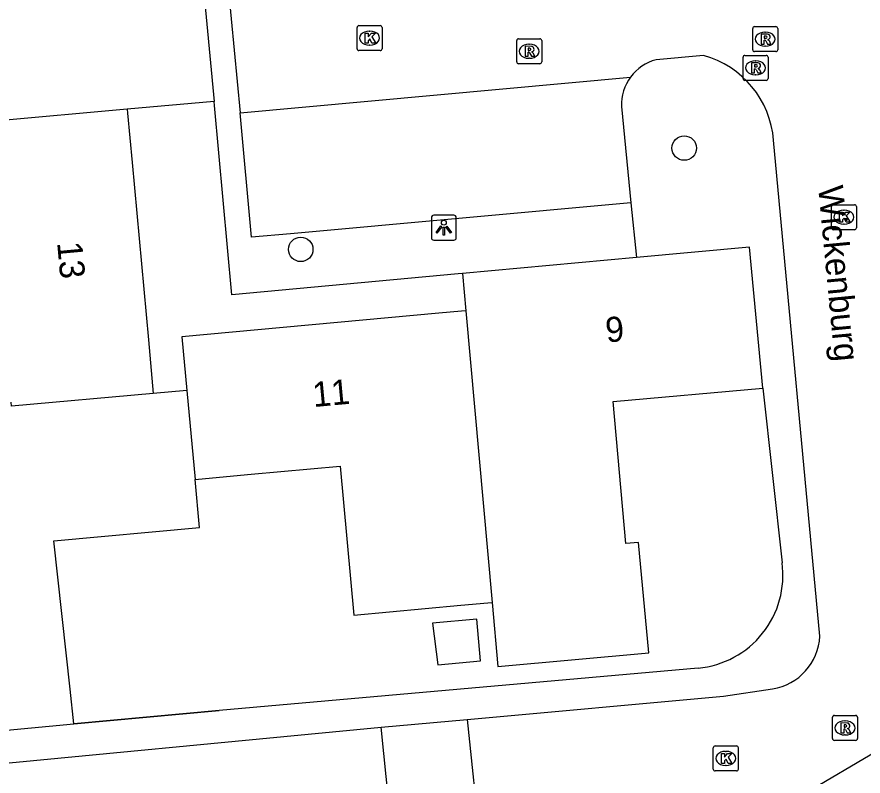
# Model space of a CAD drawing. Extents: x 157793 to 159380, y 380882 to 382313.
# Drawn here: x 158442.69 to 158476.55, y 381201.1 to 381231.47 of the extents above; entities that cross this region are included whole.
import ezdxf

# ---------------------------------------------------------------- set-up
doc = ezdxf.new("R2010")
doc.units = 0
for name, color, linetype in [('IMGEO_Boom', 7, 'Continuous'), ('IMGEO_Kolk', 7, 'Continuous'), ('IMGEO_Lichtpunt', 7, 'Continuous'), ('IMGEO_Muur', 7, 'Continuous'), ('IMGEO_Openbare_ruimte_label', 7, 'Continuous'), ('IMGEO_Pand', 7, 'Continuous'), ('IMGEO_Pand_nummerreeks', 7, 'Continuous'), ('IMGEO_Rijbaan_lokaal_open', 7, 'Continuous'), ('IMGEO_Rioolput', 7, 'Continuous'), ('IMGEO_Voetpad_open', 7, 'Continuous')]:
    doc.layers.add(name, color=color, linetype=linetype)

msp = doc.modelspace()

# ---------------------------------------------------------------- linework, layer by layer
at = {"layer": 'IMGEO_Boom'}
for centre in [(158469.389, 381226.221), (158454.045, 381222.169)]:
    msp.add_circle(centre, 0.489, dxfattribs=at)
at = {"layer": 'IMGEO_Kolk'}
for p, q in [((158456.3, 381230.196), (158456.3, 381231.048)), ((158456.375, 381231.122), (158457.227, 381231.122)), ((158456.788, 381230.902), (158456.813, 381230.902)), ((158457.301, 381231.048), (158457.301, 381230.196)), ((158456.811, 381230.342), (158456.786, 381230.342)), ((158457.227, 381230.122), (158456.375, 381230.122)), ((158475.281, 381223.031), (158475.281, 381223.883)), ((158475.356, 381223.957), (158476.208, 381223.957)), ((158475.769, 381223.737), (158475.794, 381223.737)), ((158476.282, 381223.883), (158476.282, 381223.031)), ((158475.792, 381223.177), (158475.767, 381223.177)), ((158476.208, 381222.957), (158475.356, 381222.957)), ((158470.554, 381201.38), (158470.554, 381202.232)), ((158470.629, 381202.306), (158471.481, 381202.306)), ((158471.042, 381202.086), (158471.067, 381202.086)), ((158471.555, 381202.232), (158471.555, 381201.38)), ((158471.065, 381201.526), (158471.04, 381201.526)), ((158471.481, 381201.306), (158470.629, 381201.306))]:
    msp.add_line(p, q, dxfattribs=at)
for points in [[(158456.3, 381230.196), (158456.3, 381231.048)], [(158456.375, 381231.122), (158457.227, 381231.122)], [(158457.301, 381231.048), (158457.301, 381230.196)], [(158456.621, 381230.822), (158456.744, 381230.822), (158456.744, 381230.671), (158456.874, 381230.822), (158457.038, 381230.822), (158456.892, 381230.671), (158457.045, 381230.422), (158456.893, 381230.422), (158456.808, 381230.586), (158456.744, 381230.519), (158456.744, 381230.422), (158456.621, 381230.422), (158456.621, 381230.822)], [(158457.227, 381230.122), (158456.375, 381230.122)], [(158475.281, 381223.031), (158475.281, 381223.883)], [(158475.356, 381223.957), (158476.208, 381223.957)], [(158476.282, 381223.883), (158476.282, 381223.031)], [(158475.602, 381223.657), (158475.725, 381223.657), (158475.725, 381223.506), (158475.855, 381223.657), (158476.019, 381223.657), (158475.873, 381223.506), (158476.026, 381223.257), (158475.874, 381223.257), (158475.789, 381223.421), (158475.725, 381223.354), (158475.725, 381223.257), (158475.602, 381223.257), (158475.602, 381223.657)], [(158476.208, 381222.957), (158475.356, 381222.957)], [(158470.554, 381201.38), (158470.554, 381202.232)], [(158470.629, 381202.306), (158471.481, 381202.306)], [(158471.555, 381202.232), (158471.555, 381201.38)], [(158470.875, 381202.006), (158470.998, 381202.006), (158470.998, 381201.855), (158471.128, 381202.006), (158471.292, 381202.006), (158471.146, 381201.855), (158471.299, 381201.606), (158471.147, 381201.606), (158471.062, 381201.77), (158470.998, 381201.703), (158470.998, 381201.606), (158470.875, 381201.606), (158470.875, 381202.006)], [(158471.481, 381201.306), (158470.629, 381201.306)]]:
    msp.add_lwpolyline(points, dxfattribs=at)
for centre, start, end in [((158456.377, 381231.046), 91.552, 178.448), ((158456.377, 381231.046), 91.552, 178.448), ((158457.225, 381231.046), 1.552, 88.448), ((158457.225, 381231.046), 1.552, 88.448), ((158456.377, 381230.198), 181.552, 268.448), ((158456.377, 381230.198), 181.552, 268.448), ((158457.225, 381230.198), 271.552, 358.448), ((158457.225, 381230.198), 271.552, 358.448), ((158475.358, 381223.881), 91.552, 178.448), ((158475.358, 381223.881), 91.552, 178.448), ((158476.206, 381223.881), 1.552, 88.448), ((158476.206, 381223.881), 1.552, 88.448), ((158475.358, 381223.033), 181.552, 268.448), ((158475.358, 381223.033), 181.552, 268.448), ((158476.206, 381223.033), 271.552, 358.448), ((158476.206, 381223.033), 271.552, 358.448), ((158470.631, 381202.23), 91.552, 178.448), ((158470.631, 381202.23), 91.552, 178.448), ((158471.479, 381202.23), 1.552, 88.448), ((158471.479, 381202.23), 1.552, 88.448), ((158470.631, 381201.382), 181.552, 268.448), ((158470.631, 381201.382), 181.552, 268.448), ((158471.479, 381201.382), 271.552, 358.448), ((158471.479, 381201.382), 271.552, 358.448)]:
    msp.add_arc(centre, 0.0765, start, end, dxfattribs=at)
for centre, major_axis, ratio, start_param, end_param in [((158456.787, 381230.622), (-0.387, 0.002), 0.722429, 4.712389, 7.853982), ((158456.812, 381230.622), (-0.39, 0.002), 0.717154, 1.570796, 4.712389), ((158475.768, 381223.457), (-0.387, 0.002), 0.722429, 4.712389, 7.853982), ((158475.793, 381223.457), (-0.39, 0.002), 0.717154, 1.570796, 4.712389), ((158471.041, 381201.806), (-0.387, 0.002), 0.722429, 4.712389, 7.853982), ((158471.066, 381201.806), (-0.39, 0.002), 0.717154, 1.570796, 4.712389)]:
    msp.add_ellipse(centre, major_axis=major_axis, ratio=ratio, start_param=start_param, end_param=end_param, dxfattribs=at)
at = {"layer": 'IMGEO_Lichtpunt'}
for p, q in [((158459.271, 381223.441), (158459.271, 381222.634)), ((158459.271, 381223.441), (158459.271, 381222.634)), ((158460.173, 381223.536), (158459.365, 381223.536)), ((158460.173, 381223.536), (158459.365, 381223.536)), ((158460.267, 381222.634), (158460.267, 381223.441)), ((158460.267, 381222.634), (158460.267, 381223.441)), ((158459.365, 381222.54), (158460.173, 381222.54)), ((158459.365, 381222.54), (158460.173, 381222.54))]:
    msp.add_line(p, q, dxfattribs=at)
for points in [[(158459.645, 381223.105), (158459.684, 381223.077), (158459.496, 381222.815), (158459.458, 381222.842), (158459.645, 381223.105)], [(158459.747, 381223.057), (158459.794, 381223.057), (158459.794, 381222.735), (158459.747, 381222.735), (158459.747, 381223.057)], [(158459.857, 381223.077), (158459.895, 381223.104), (158460.082, 381222.842), (158460.043, 381222.814), (158459.857, 381223.077)]]:
    msp.add_lwpolyline(points, dxfattribs=at)
msp.add_circle((158459.77, 381223.239), 0.0994, dxfattribs=at)
for centre, start, end in [((158459.365, 381223.441), 90, 180), ((158459.365, 381223.441), 90, 180), ((158460.173, 381223.441), 0, 90), ((158460.173, 381223.441), 0, 90), ((158459.365, 381222.634), 180, 270), ((158459.365, 381222.634), 180, 270), ((158460.173, 381222.634), 270, 0), ((158460.173, 381222.634), 270, 360)]:
    msp.add_arc(centre, 0.0946, start, end, dxfattribs=at)
at = {"layer": 'IMGEO_Muur'}
msp.add_lwpolyline([(158444.965, 381203.195), (158450.78, 381203.721)], dxfattribs=at)
at = {"layer": 'IMGEO_Pand'}
for points in [[(158449.498, 381239.486), (158450.574, 381228.089)], [(158450.574, 381228.089), (158447.099, 381227.776)], [(158447.099, 381227.776), (158441.791, 381227.299), (158441.772, 381227.505)], [(158447.099, 381227.776), (158447.114, 381227.613), (158447.295, 381225.643), (158447.946, 381218.547), (158448.143, 381216.4)], [(158472.539, 381216.612), (158471.997, 381222.264), (158467.485, 381221.848)], [(158467.485, 381221.848), (158460.511, 381221.203)], [(158460.511, 381221.203), (158460.646, 381219.714)], [(158460.646, 381219.714), (158460.475, 381219.698), (158459.575, 381219.615), (158449.287, 381218.67), (158449.486, 381216.519)], [(158460.646, 381219.714), (158461.699, 381208.046)], [(158448.143, 381216.4), (158442.469, 381215.898), (158442.454, 381216.063)], [(158449.486, 381216.519), (158448.143, 381216.4)], [(158449.486, 381216.519), (158449.815, 381212.97)], [(158461.699, 381208.046), (158461.931, 381205.481), (158467.98, 381206.029), (158467.56, 381210.447), (158467.052, 381210.402), (158466.55, 381216.082), (158472.539, 381216.612)], [(158449.815, 381212.97), (158449.952, 381212.983), (158452.059, 381213.175), (158455.625, 381213.5), (158456.17, 381207.54), (158460.444, 381207.931), (158461.527, 381208.03), (158461.699, 381208.046)], [(158444.965, 381203.195), (158444.822, 381204.576), (158444.165, 381210.51), (158449.993, 381211.043), (158449.815, 381212.97)], [(158459.322, 381207.212), (158459.531, 381205.546), (158461.243, 381205.703), (158461.09, 381207.373), (158459.322, 381207.212)], [(158440.577, 381202.778), (158444.965, 381203.195)]]:
    msp.add_lwpolyline(points, dxfattribs=at)
at = {"layer": 'IMGEO_Rijbaan_lokaal_open'}
for points in [[(158453.64, 381232.867), (158451.137, 381232.661), (158451.618, 381227.629)], [(158470.163, 381229.924), (158468.263, 381229.754)], [(158451.618, 381227.629), (158467.244, 381229.063)], [(158474.817, 381206.693), (158472.968, 381226.538)], [(158460.708, 381203.357), (158470.963, 381204.292), (158472.924, 381204.592)], [(158457.257, 381203.058), (158460.708, 381203.357)], [(158460.708, 381203.357), (158461.221, 381198.372)], [(158479.141, 381203.293), (158472.219, 381199.216)], [(158439.448, 381201.343), (158457.257, 381203.058)], [(158457.774, 381198.055), (158457.257, 381203.058)]]:
    msp.add_lwpolyline(points, dxfattribs=at)
for centre, radius, start, end in [((158469.158, 381226.237), 3.822, 4.5225, 74.755), ((158468.729, 381227.97), 1.844, 104.6356, 143.648), ((158472.585, 381206.801), 2.235, 278.7355, 357.2268)]:
    msp.add_arc(centre, radius, start, end, dxfattribs=at)
at = {"layer": 'IMGEO_Rioolput'}
for p, q in [((158472.131, 381230.155), (158472.131, 381231.007)), ((158472.206, 381231.081), (158473.058, 381231.081)), ((158472.619, 381230.861), (158472.644, 381230.861)), ((158473.132, 381231.007), (158473.132, 381230.155)), ((158462.685, 381229.668), (158462.685, 381230.52)), ((158462.76, 381230.594), (158463.612, 381230.594)), ((158463.686, 381230.52), (158463.686, 381229.668)), ((158463.173, 381230.374), (158463.198, 381230.374)), ((158472.642, 381230.301), (158472.617, 381230.301)), ((158471.744, 381229.005), (158471.744, 381229.857)), ((158471.819, 381229.931), (158472.671, 381229.931)), ((158473.058, 381230.081), (158472.206, 381230.081)), ((158472.745, 381229.857), (158472.745, 381229.005)), ((158463.612, 381229.594), (158462.76, 381229.594)), ((158463.196, 381229.814), (158463.171, 381229.814)), ((158472.232, 381229.711), (158472.257, 381229.711)), ((158472.255, 381229.151), (158472.23, 381229.151)), ((158472.671, 381228.931), (158471.819, 381228.931)), ((158475.323, 381202.598), (158475.323, 381203.45)), ((158475.398, 381203.524), (158476.25, 381203.524)), ((158476.324, 381203.45), (158476.324, 381202.598)), ((158475.811, 381203.304), (158475.836, 381203.304)), ((158475.834, 381202.744), (158475.809, 381202.744)), ((158476.25, 381202.524), (158475.398, 381202.524))]:
    msp.add_line(p, q, dxfattribs=at)
for points in [[(158472.131, 381230.155), (158472.131, 381231.007)], [(158472.206, 381231.081), (158473.058, 381231.081)], [(158473.132, 381231.007), (158473.132, 381230.155)], [(158462.685, 381229.668), (158462.685, 381230.52)], [(158462.76, 381230.594), (158463.612, 381230.594)], [(158463.686, 381230.52), (158463.686, 381229.668)], [(158472.72, 381230.779), (158472.468, 381230.781), (158472.468, 381230.381)], [(158472.468, 381230.381), (158472.592, 381230.381), (158472.592, 381230.543), (158472.603, 381230.543)], [(158472.646, 381230.7), (158472.592, 381230.7), (158472.592, 381230.619)], [(158472.592, 381230.619), (158472.644, 381230.619)], [(158472.65, 381230.514), (158472.721, 381230.381), (158472.861, 381230.381), (158472.796, 381230.507)], [(158463.274, 381230.292), (158463.022, 381230.294), (158463.022, 381229.894)], [(158463.2, 381230.213), (158463.146, 381230.213), (158463.146, 381230.132)], [(158463.022, 381229.894), (158463.146, 381229.894), (158463.146, 381230.056), (158463.157, 381230.056)], [(158463.146, 381230.132), (158463.198, 381230.132)], [(158463.204, 381230.027), (158463.275, 381229.894), (158463.415, 381229.894), (158463.35, 381230.02)], [(158471.744, 381229.005), (158471.744, 381229.857)], [(158471.819, 381229.931), (158472.671, 381229.931)], [(158473.058, 381230.081), (158472.206, 381230.081)], [(158472.745, 381229.857), (158472.745, 381229.005)], [(158463.612, 381229.594), (158462.76, 381229.594)], [(158472.333, 381229.629), (158472.081, 381229.631), (158472.081, 381229.231)], [(158472.259, 381229.55), (158472.205, 381229.55), (158472.205, 381229.469)], [(158472.081, 381229.231), (158472.205, 381229.231), (158472.205, 381229.393), (158472.216, 381229.393)], [(158472.205, 381229.469), (158472.257, 381229.469)], [(158472.263, 381229.364), (158472.334, 381229.231), (158472.474, 381229.231), (158472.409, 381229.357)], [(158472.671, 381228.931), (158471.819, 381228.931)], [(158475.323, 381202.598), (158475.323, 381203.45)], [(158475.398, 381203.524), (158476.25, 381203.524)], [(158476.324, 381203.45), (158476.324, 381202.598)], [(158475.912, 381203.222), (158475.66, 381203.224), (158475.66, 381202.824)], [(158475.838, 381203.143), (158475.784, 381203.143), (158475.784, 381203.062)], [(158475.66, 381202.824), (158475.784, 381202.824), (158475.784, 381202.986), (158475.795, 381202.986)], [(158475.784, 381203.062), (158475.836, 381203.062)], [(158475.842, 381202.957), (158475.913, 381202.824), (158476.053, 381202.824), (158475.988, 381202.95)], [(158476.25, 381202.524), (158475.398, 381202.524)]]:
    msp.add_lwpolyline(points, dxfattribs=at)
for centre, radius, start, end in [((158472.208, 381231.005), 0.0765, 91.552, 178.448), ((158472.208, 381231.005), 0.0765, 91.552, 178.448), ((158473.056, 381231.005), 0.0765, 1.552, 88.448), ((158473.056, 381231.005), 0.0765, 1.552, 88.448), ((158462.762, 381230.518), 0.0765, 91.552, 178.448), ((158462.762, 381230.518), 0.0765, 91.552, 178.448), ((158463.61, 381230.518), 0.0765, 1.552, 88.448), ((158463.61, 381230.518), 0.0765, 1.552, 88.448), ((158472.602, 381230.49), 0.0533, 26.0293, 88.6989), ((158472.628, 381230.808), 0.19, 274.7715, 282.9687), ((158472.652, 381230.604), 0.0964, 77.0061, 93.1865), ((158472.666, 381230.661), 0.0378, 276.6634, 79.6772), ((158472.719, 381230.669), 0.109, 350.3612, 89.416), ((158472.717, 381230.669), 0.112, 277.5842, 350.9817), ((158472.701, 381230.454), 0.108, 29.5134, 73.7905), ((158463.206, 381230.117), 0.0964, 77.0061, 93.1865), ((158463.22, 381230.174), 0.0378, 276.6634, 79.6772), ((158463.273, 381230.182), 0.109, 350.3612, 89.416), ((158463.271, 381230.182), 0.112, 277.5842, 350.9817), ((158463.156, 381230.003), 0.0533, 26.0293, 88.6989), ((158463.182, 381230.321), 0.19, 274.7715, 282.9687), ((158463.255, 381229.967), 0.108, 29.5134, 73.7905), ((158471.821, 381229.855), 0.0765, 91.552, 178.448), ((158471.821, 381229.855), 0.0765, 91.552, 178.448), ((158472.208, 381230.157), 0.0765, 181.552, 268.448), ((158472.208, 381230.157), 0.0765, 181.552, 268.448), ((158472.669, 381229.855), 0.0765, 1.552, 88.448), ((158472.669, 381229.855), 0.0765, 1.552, 88.448), ((158473.056, 381230.157), 0.0765, 271.552, 358.448), ((158473.056, 381230.157), 0.0765, 271.552, 358.448), ((158462.762, 381229.67), 0.0765, 181.552, 268.448), ((158462.762, 381229.67), 0.0765, 181.552, 268.448), ((158463.61, 381229.67), 0.0765, 271.552, 358.448), ((158463.61, 381229.67), 0.0765, 271.552, 358.448), ((158472.265, 381229.454), 0.0964, 77.0061, 93.1865), ((158472.279, 381229.511), 0.0378, 276.6634, 79.6772), ((158472.332, 381229.519), 0.109, 350.3612, 89.416), ((158472.33, 381229.519), 0.112, 277.5842, 350.9817), ((158472.215, 381229.34), 0.0533, 26.0293, 88.6989), ((158472.241, 381229.658), 0.19, 274.7715, 282.9687), ((158472.314, 381229.304), 0.108, 29.5134, 73.7905), ((158471.821, 381229.007), 0.0765, 181.552, 268.448), ((158471.821, 381229.007), 0.0765, 181.552, 268.448), ((158472.669, 381229.007), 0.0765, 271.552, 358.448), ((158472.669, 381229.007), 0.0765, 271.552, 358.448), ((158475.4, 381203.448), 0.0765, 91.552, 178.448), ((158475.4, 381203.448), 0.0765, 91.552, 178.448), ((158476.248, 381203.448), 0.0765, 1.552, 88.448), ((158476.248, 381203.448), 0.0765, 1.552, 88.448), ((158475.844, 381203.047), 0.0964, 77.0061, 93.1865), ((158475.858, 381203.104), 0.0378, 276.6634, 79.6772), ((158475.911, 381203.112), 0.109, 350.3612, 89.416), ((158475.909, 381203.112), 0.112, 277.5842, 350.9817), ((158475.794, 381202.933), 0.0533, 26.0293, 88.6989), ((158475.82, 381203.251), 0.19, 274.7715, 282.9687), ((158475.893, 381202.897), 0.108, 29.5134, 73.7905), ((158475.4, 381202.6), 0.0765, 181.552, 268.448), ((158475.4, 381202.6), 0.0765, 181.552, 268.448), ((158476.248, 381202.6), 0.0765, 271.552, 358.448), ((158476.248, 381202.6), 0.0765, 271.552, 358.448)]:
    msp.add_arc(centre, radius, start, end, dxfattribs=at)
for centre, major_axis, ratio, start_param, end_param in [((158472.618, 381230.581), (-0.387, 0.002), 0.722429, 4.712389, 7.853982), ((158472.643, 381230.581), (-0.39, 0.002), 0.717154, 1.570796, 4.712389), ((158463.172, 381230.094), (-0.387, 0.002), 0.722429, 4.712389, 7.853982), ((158463.197, 381230.094), (-0.39, 0.002), 0.717154, 1.570796, 4.712389), ((158472.231, 381229.431), (-0.387, 0.002), 0.722429, 4.712389, 7.853982), ((158472.256, 381229.431), (-0.39, 0.002), 0.717154, 1.570796, 4.712389), ((158475.81, 381203.024), (-0.387, 0.002), 0.722429, 4.712389, 7.853982), ((158475.835, 381203.024), (-0.39, 0.002), 0.717154, 1.570796, 4.712389)]:
    msp.add_ellipse(centre, major_axis=major_axis, ratio=ratio, start_param=start_param, end_param=end_param, dxfattribs=at)
at = {"layer": 'IMGEO_Voetpad_open'}
for points in [[(158460.511, 381221.203), (158460.338, 381221.187), (158451.284, 381220.351), (158450.589, 381227.932), (158450.574, 381228.089)], [(158466.884, 381227.887), (158467.257, 381224.032)], [(158467.257, 381224.032), (158453.639, 381222.798), (158452.068, 381222.655), (158451.618, 381227.629)], [(158467.257, 381224.032), (158467.485, 381221.848)], [(158472.539, 381216.612), (158473.308, 381209.636)], [(158469.948, 381205.42), (158450.78, 381203.721), (158444.965, 381203.195)]]:
    msp.add_lwpolyline(points, dxfattribs=at)
for centre, radius, start, end in [((158468.725, 381227.967), 1.842, 143.4821, 182.4768), ((158469.609, 381209.137), 3.733, 275.2128, 7.6801)]:
    msp.add_arc(centre, radius, start, end, dxfattribs=at)

# ---------------------------------------------------------------- texts
at = {"layer": 'IMGEO_Openbare_ruimte_label'}
msp.add_text('Wickenburg', height=1, rotation=275.4539, dxfattribs=at).set_placement((158474.746, 381224.677))
at = {"layer": 'IMGEO_Pand_nummerreeks'}
for s, rotation, p in [('13', 275.2424, (158444.295, 381222.439)), ('9', 5.2769, (158466.282, 381218.442)), ('11', 5.2483, (158454.562, 381215.86))]:
    msp.add_text(s, height=1, rotation=rotation, dxfattribs=at).set_placement(p)

doc.saveas('drawing.dxf')
